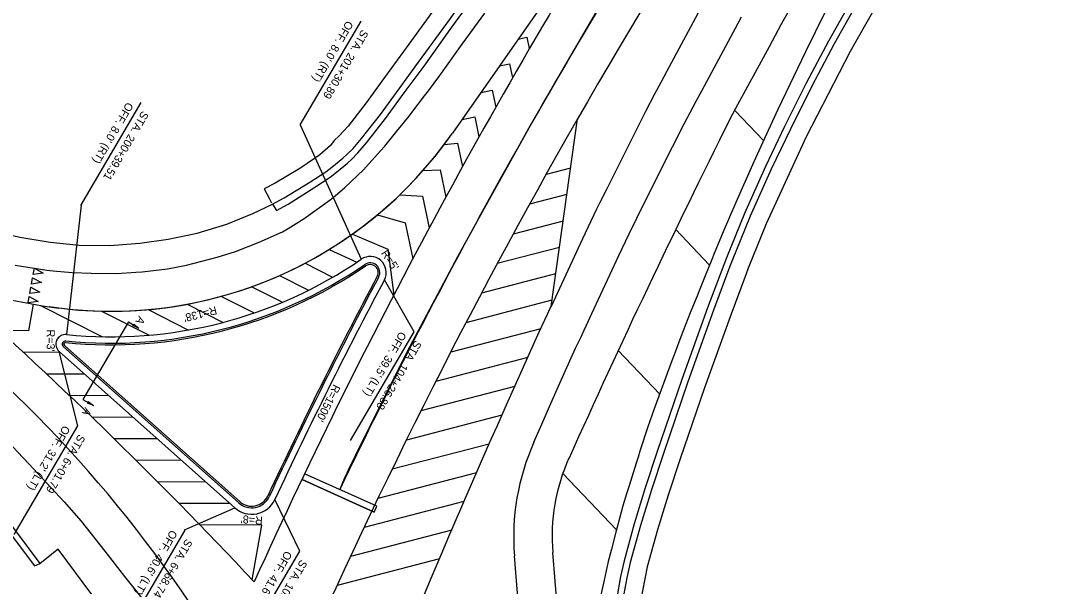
# Model space of a CAD drawing. Extents: x 1730210 to 1732101, y 650763 to 653427.
# Drawn here: x 1730371.6 to 1730692.6, y 652950.2 to 653127 of the extents above; entities that cross this region are included whole.
import ezdxf

# ---------------------------------------------------------------- set-up
doc = ezdxf.new("R2010")
doc.units = 0
for name, color, linetype in [('DESIGN - SCRATCH - User 2', 7, 'Continuous'), ('DESIGN - TRAFFIC CONTROL PERMANENT - Pavement Marking', 7, 'Continuous'), ('DESIGN - TRANSPORTATION - Curb Gutter and Sidewalk', 7, 'Continuous'), ('DESIGN - TRANSPORTATION - Edge of Traveled Way', 7, 'Continuous'), ('DESIGN - TRANSPORTATION - Text', 7, 'Continuous'), ('FUNCTIONAL - TRANSPORTATION - Pavement Marking and Traffic Control', 7, 'Continuous'), ('FUNCTIONAL - TRANSPORTATION - Preliminary Edge of Traveled Way', 7, 'Continuous'), ('SURVEY - ROADSIDE BARRIERS with Text', 7, 'Continuous'), ('SURVEY - TRANSPORTATION - Features', 7, 'Continuous')]:
    doc.layers.add(name, color=color, linetype=linetype)

msp = doc.modelspace()

# ---------------------------------------------------------------- linework, layer by layer
at = {"layer": 'DESIGN - SCRATCH - User 2'}
msp.add_lwpolyline([(1730588.17, 653054.17), (1730587.43, 653052.31), (1730585.19, 653046.75), (1730583.7, 653043.05), (1730582.96, 653041.2), (1730580.72, 653035.64), (1730579.98, 653033.79), (1730579.23, 653031.93), (1730578.49, 653030.08), (1730577.77, 653028.22), (1730575.7, 653022.59), (1730575.01, 653020.72), (1730569.51, 653005.72), (1730567.44, 653000.09), (1730565.01, 652992.48), (1730564.42, 652990.58), (1730563.82, 652988.67), (1730562.03, 652982.96), (1730561.43, 652981.05), (1730560.83, 652979.14), (1730559.66, 652975.33), (1730558.65, 652971.46), (1730557.64, 652967.6), (1730556.13, 652961.81), (1730555.12, 652957.94), (1730553.8, 652952.1), (1730552.12, 652944.29)], dxfattribs=at)
at = {"layer": 'DESIGN - TRAFFIC CONTROL PERMANENT - Pavement Marking'}
for p, q in [((1730568.54, 653180.87), (1730506.46, 653091.82)), ((1730526.94, 653121.19), (1730529.73, 653121.77)), ((1730529.73, 653121.77), (1730530.47, 653118.21)), ((1730521.11, 653112.83), (1730524.3, 653113.49)), ((1730524.3, 653113.49), (1730525.21, 653109.1)), ((1730515.28, 653104.47), (1730518.87, 653105.21)), ((1730518.87, 653105.21), (1730519.97, 653099.91)), ((1730594.64, 653098.91), (1730603.58, 653089.49)), ((1730509.45, 653096.11), (1730513.44, 653096.94)), ((1730513.44, 653096.94), (1730514.75, 653090.63)), ((1730537.24, 653037.62), (1730545.53, 653096.29)), ((1730503.86, 653088.22), (1730508.01, 653088.66)), ((1730508.01, 653088.66), (1730509.55, 653081.25)), ((1730497.32, 653080.17), (1730502.58, 653080.38)), ((1730502.58, 653080.38), (1730504.37, 653071.78)), ((1730543.35, 653080.88), (1730535.68, 653078.88)), ((1730490.01, 653072.53), (1730497.15, 653072.1)), ((1730497.15, 653072.1), (1730499.21, 653062.22)), ((1730542.19, 653072.62), (1730530.52, 653069.58)), ((1730483.01, 653066.27), (1730491.72, 653063.82)), ((1730491.72, 653063.82), (1730494.06, 653052.56)), ((1730541.02, 653064.36), (1730525.45, 653060.3)), ((1730475.21, 653060.26), (1730486.29, 653055.54)), ((1730576.18, 653061.71), (1730586.69, 653050.64)), ((1730468, 653055.48), (1730476.64, 653051.53)), ((1730486.29, 653055.54), (1730488.11, 653041.2)), ((1730539.85, 653056.1), (1730520.45, 653051.05)), ((1730460.41, 653051.15), (1730469.04, 653046.79)), ((1730452.48, 653047.31), (1730461.54, 653042.74)), ((1730538.68, 653047.84), (1730515.53, 653041.81)), ((1730443.83, 653043.84), (1730453.41, 653039)), ((1730434.29, 653040.82), (1730444.57, 653035.63)), ((1730537.52, 653039.58), (1730510.69, 653032.59)), ((1730537.52, 653039.58), (1730510.69, 653032.59)), ((1730374.16, 653030.08), (1730375.61, 653038.36)), ((1730377.79, 653038), (1730397.2, 653028.19)), ((1730396.87, 653036.2), (1730411.75, 653028.68)), ((1730411.43, 653036.69), (1730424.05, 653030.31)), ((1730423.63, 653038.37), (1730434.86, 653032.69)), ((1730374.16, 653030.08), (1730365.08, 653030.13)), ((1730534.02, 653030.71), (1730505.92, 653023.39)), ((1730383.94, 653023.33), (1730372.4, 653023.39)), ((1730558.25, 653023.94), (1730571.19, 653010.31)), ((1730529.98, 653021.7), (1730501.23, 653014.22)), ((1730391.62, 653016.5), (1730379.72, 653016.56)), ((1730525.95, 653012.7), (1730496.61, 653005.06)), ((1730399.18, 653009.76), (1730386.83, 653009.82)), ((1730406.75, 653003.02), (1730393.86, 653003.09)), ((1730521.92, 653003.69), (1730492.07, 652995.92)), ((1730414.31, 652996.28), (1730400.78, 652996.35)), ((1730517.9, 652994.69), (1730487.6, 652986.8)), ((1730421.87, 652989.54), (1730407.62, 652989.62)), ((1730513.97, 652985.71), (1730483.2, 652977.7)), ((1730540.95, 652985.52), (1730557.71, 652967.86)), ((1730429.44, 652982.8), (1730414.36, 652982.88)), ((1730482.06, 652973.4), (1730459.48, 652983.59)), ((1730437, 652976.06), (1730421.02, 652976.15)), ((1730510.05, 652976.73), (1730478.86, 652968.61)), ((1730446.88, 652969.31), (1730427.59, 652969.41)), ((1730443.91, 652952.29), (1730446.88, 652969.31)), ((1730506.22, 652967.77), (1730474.6, 652959.54)), ((1730534.26, 652857.53), (1730525.83, 652959.78)), ((1730546.22, 652858.52), (1730537.78, 652960.76)), ((1730502.38, 652958.82), (1730470.41, 652950.5))]:
    msp.add_line(p, q, dxfattribs=at)
for points in [[(1730593.11, 653096.12), (1730595.01, 653099.58), (1730605.44, 653118.92), (1730606.39, 653120.68), (1730607.32, 653122.42), (1730609.17, 653125.81), (1730610.1, 653127.46), (1730620.96, 653146.57), (1730627.78, 653158.58), (1730630.78, 653163.54), (1730640.18, 653178.84), (1730649.49, 653194.01), (1730672.51, 653228.86), (1730678.04, 653237.13), (1730683.11, 653244.69)], [(1730594.14, 653148.92), (1730588.79, 653139.5), (1730587.75, 653137.67), (1730585.78, 653134.04), (1730584.82, 653132.27), (1730583.87, 653130.51), (1730573.44, 653111.17), (1730571.55, 653107.65), (1730569.6, 653104.04), (1730566.77, 653098.56), (1730554.35, 653073.78)], [(1730369.89, 653050.6), (1730375.78, 653049.62), (1730379.73, 653049.04), (1730381.71, 653048.83), (1730387.67, 653048.28), (1730393.64, 653048.02), (1730401.62, 653047.99), (1730407.59, 653048.35), (1730409.58, 653048.47), (1730417.49, 653049.46), (1730423.37, 653050.53), (1730433, 653053.08), (1730438.71, 653054.8), (1730446.12, 653057.73), (1730453.4, 653060.99), (1730455.1, 653062.03), (1730460.19, 653065.18), (1730463.45, 653067.5), (1730468.3, 653071), (1730469.84, 653072.28), (1730472.9, 653074.84), (1730478.67, 653080.37), (1730484.04, 653086.28), (1730485.38, 653087.77), (1730489.14, 653092.44), (1730492.9, 653097.1), (1730494.12, 653098.67), (1730497.78, 653103.42), (1730499, 653105), (1730502.51, 653109.86), (1730509.49, 653119.6), (1730516.54, 653129.3)], [(1730471.25, 652980.39), (1730472.79, 652983.87), (1730473.6, 652985.7), (1730474.44, 652987.51), (1730476.13, 652991.13), (1730481.48, 653001.85), (1730492.24, 653023.27), (1730494.09, 653026.81), (1730508.17, 653053.26), (1730514.89, 653065.53), (1730530.41, 653093.47), (1730534.41, 653100.39), (1730542.44, 653114.2), (1730551.48, 653129.75)], [(1730531.92, 652995.23), (1730534.34, 653000.89), (1730536.79, 653006.36), (1730540.05, 653013.65), (1730544.94, 653024.59), (1730546.63, 653028.21), (1730547.47, 653030.02), (1730548.32, 653031.83), (1730550, 653035.45), (1730558.43, 653053.55), (1730562.7, 653062.58), (1730563.59, 653064.36), (1730564.49, 653066.15), (1730575.23, 653087.57), (1730577.02, 653091.14), (1730577.91, 653092.92), (1730580.66, 653098.25), (1730581.6, 653100.01), (1730582.55, 653101.76), (1730584.45, 653105.28), (1730594.88, 653124.62), (1730595.82, 653126.38), (1730596.77, 653128.13)], [(1730554.35, 653073.78), (1730552.42, 653069.94), (1730551.46, 653068.02), (1730547.12, 653058.84), (1730537.24, 653037.62)], [(1730279.88, 653060.81), (1730281.86, 653059.79), (1730290.11, 653055.41), (1730298.77, 653050.43), (1730306.79, 653045.43), (1730315.16, 653039.98), (1730322.67, 653034.75), (1730331.63, 653027.94), (1730338.9, 653022.07), (1730346.44, 653015.53), (1730353.22, 653009.5), (1730360.49, 653002.64), (1730367.3, 652995.75), (1730374.2, 652988.52), (1730385.19, 652976.62)], [(1730518.03, 652994.99), (1730518.04, 652995.02), (1730519.68, 652998.69), (1730520.5, 653000.51), (1730522.95, 653005.98), (1730533.58, 653029.76), (1730535.31, 653033.47), (1730536.15, 653035.28), (1730536.99, 653037.09), (1730537.24, 653037.62)], [(1730459.75, 652854.49), (1730462.34, 652861.01), (1730463.81, 652864.72), (1730464.55, 652866.58), (1730467.49, 652874.01), (1730478.69, 652901.8), (1730487.06, 652922.11), (1730491.64, 652933.19), (1730494.71, 652940.56), (1730500.09, 652953.46), (1730503.24, 652960.81), (1730505.59, 652966.32), (1730506.38, 652968.16), (1730507.95, 652971.83), (1730508.73, 652973.66), (1730510.3, 652977.33), (1730518.04, 652995.02)], [(1730385.19, 652976.62), (1730390.46, 652970.6), (1730397.86, 652961.16), (1730404.04, 652953.3), (1730407.74, 652948.58), (1730408.98, 652947.01), (1730410.08, 652945.35), (1730414.32, 652938.57), (1730416.33, 652935.1), (1730417.24, 652933.33), (1730418.1, 652931.52), (1730418.91, 652929.69), (1730420.24, 652925.92), (1730421.36, 652922.08), (1730421.91, 652920.16), (1730422.75, 652916.25), (1730423.43, 652910.3), (1730423.58, 652908.3), (1730423.67, 652903.38)]]:
    msp.add_lwpolyline(points, dxfattribs=at)
for points in [[(1730375.53, 653047.62), (1730375.89, 653049.59), (1730378.67, 653048.06)], [(1730374.99, 653044.67), (1730375.35, 653046.63), (1730378.13, 653045.11)], [(1730374.45, 653041.72), (1730374.81, 653043.68), (1730377.59, 653042.16)], [(1730373.91, 653038.76), (1730374.27, 653040.73), (1730377.05, 653039.21)], [(1730482.06, 652973.4), (1730482.88, 652975.22), (1730460.3, 652985.41), (1730459.48, 652983.59)]]:
    msp.add_lwpolyline(points, close=True, dxfattribs=at)
for centre, radius, start, end in [((1732146.89, 652178.93), 1845.51, 143.31109, 155.90666), ((1732146.89, 652178.93), 1869.51, 147.59272, 155.58683), ((1733115.88, 651833.24), 2821.21, 153.40774, 155.78687), ((1730399.81, 653166.17), 130.01, 261.4471, 325.1194), ((1730399.81, 653166.17), 130, 262.7955, 325.1194), ((1730406.08, 653215.77), 180.01, 251.24, 262.7955), ((1729392.41, 651966.14), 1441.58, 43.127, 48.47054), ((1730082.94, 652714.55), 412, 31.4096, 52.3723), ((1730597.58, 652965.7), 72, 155.7869, 184.7177), ((1730597.58, 652965.7), 60, 155.7869, 184.7177)]:
    msp.add_arc(centre, radius, start, end, dxfattribs=at)
at = {"layer": 'DESIGN - TRANSPORTATION - Curb Gutter and Sidewalk'}
for p, q in [((1730383.59, 653023.64), (1730438.45, 652974.77)), ((1730384.92, 653025.14), (1730439.78, 652976.27)), ((1730385.25, 653025.51), (1730440.11, 652976.64))]:
    msp.add_line(p, q, dxfattribs=at)
for centre, radius, start, end in [((1730399.81, 653166.17), 138, 264.2103, 304.4848), ((1730480.77, 653048.29), 5, 332.0531, 124.4848), ((1730399.81, 653166.17), 140.5, 264.2103, 304.472), ((1730399.81, 653166.17), 140, 264.2103, 304.472), ((1730480.77, 653048.29), 3, 332.0531, 124.4848), ((1730480.77, 653048.29), 2.5, 332.0531, 124.4848), ((1731810.26, 652342.97), 1502.5, 152.05305, 154.98031), ((1731810.26, 652342.97), 1502, 152.05305, 154.98031), ((1731810.26, 652342.97), 1500, 152.05305, 154.98031), ((1730385.59, 653025.88), 3, 84.2103, 228.3045), ((1730385.59, 653025.88), 1, 84.2103, 228.3045), ((1730385.59, 653025.88), 0.5, 84.2103, 228.3045), ((1730443.77, 652980.75), 5.5, 228.3045, 334.9803), ((1730443.77, 652980.75), 8, 228.3045, 334.9803), ((1730443.77, 652980.75), 6, 228.3045, 334.9803)]:
    msp.add_arc(centre, radius, start, end, dxfattribs=at)
at = {"layer": 'DESIGN - TRANSPORTATION - Edge of Traveled Way'}
for points in [[(1730685.53, 653248.11), (1730680.77, 653239.34), (1730670.06, 653220.12), (1730660.59, 653202.51), (1730654.94, 653191.92), (1730650.25, 653183.09), (1730645.61, 653174.24), (1730639.17, 653161.81), (1730632.82, 653149.35), (1730631.91, 653147.57), (1730628.28, 653140.45), (1730624.67, 653133.32), (1730623.78, 653131.53), (1730622.89, 653129.74), (1730616.69, 653117.22), (1730608.05, 653099.23), (1730603.89, 653090.16), (1730600.58, 653082.9), (1730594.95, 653070.11), (1730591.02, 653060.94), (1730588.7, 653055.42), (1730588.17, 653054.17)], [(1730588.17, 653054.17), (1730587.43, 653052.31), (1730585.19, 653046.75), (1730583.7, 653043.05), (1730582.96, 653041.2), (1730580.72, 653035.64), (1730579.98, 653033.79), (1730579.23, 653031.93), (1730578.49, 653030.08), (1730577.77, 653028.22), (1730575.7, 653022.59), (1730575.01, 653020.72), (1730569.51, 653005.72), (1730567.44, 653000.09), (1730565.01, 652992.48), (1730564.42, 652990.58), (1730563.82, 652988.67), (1730562.03, 652982.96), (1730561.43, 652981.05), (1730560.83, 652979.14), (1730559.66, 652975.33), (1730558.65, 652971.46), (1730557.64, 652967.6), (1730556.13, 652961.81), (1730555.12, 652957.94), (1730553.8, 652952.1), (1730552.12, 652944.29)]]:
    msp.add_lwpolyline(points, dxfattribs=at)
at = {"layer": 'DESIGN - TRANSPORTATION - Text'}
for p, q in [((1730458.91, 653094.42), (1730477.93, 653126.84)), ((1730390.36, 653069.16), (1730409.27, 653101.39)), ((1730405.26, 653032.85), (1730391.04, 653008.62)), ((1730405.26, 653032.85), (1730408.53, 653030.93)), ((1730474.58, 652995.74), (1730494.53, 653029.74)), ((1730391.04, 653008.62), (1730394.3, 653006.7)), ((1730369.55, 652966.4), (1730389.5, 653000.4)), ((1730403.05, 652933.75), (1730423, 652967.74)), ((1730438.87, 652927.22), (1730458.82, 652961.22))]:
    msp.add_line(p, q, dxfattribs=at)
for points in [[(1730458.91, 653094.42), (1730477.94, 653052.42)], [(1730390.47, 653069.35), (1730385.89, 653028.87)], [(1730494.53, 653029.74), (1730485.19, 653045.95)], [(1730408.53, 653030.93), (1730406.67, 653031.74), (1730407.02, 653031.82), (1730406.92, 653032.18), (1730408.53, 653030.93)], [(1730389.5, 653000.4), (1730383.59, 653023.64)], [(1730394.3, 653006.7), (1730392.44, 653007.5), (1730392.8, 653007.59), (1730392.7, 653007.94), (1730394.3, 653006.7)], [(1730458.82, 652961.22), (1730451.02, 652977.36)], [(1730422.81, 652967.85), (1730438.45, 652974.77)]]:
    msp.add_lwpolyline(points, dxfattribs=at)
for points in [[(1730408.53, 653030.93), (1730406.67, 653031.74), (1730407.02, 653031.82), (1730406.92, 653032.18)], [(1730394.3, 653006.7), (1730392.44, 653007.5), (1730392.8, 653007.59), (1730392.7, 653007.94)]]:
    msp.add_lwpolyline(points, close=True, dxfattribs=at)
at = {"layer": 'FUNCTIONAL - TRANSPORTATION - Pavement Marking and Traffic Control'}
for centre, radius, start, end in [((1732146.89, 652178.93), 1869.51, 147.59272, 155.58683), ((1732134.98, 652182.29), 1845.28, 147.53511, 154.37062), ((1730399.81, 653166.17), 130.01, 261.4471, 325.1194), ((1729392.41, 651966.14), 1441.58, 43.127, 48.47054)]:
    msp.add_arc(centre, radius, start, end, dxfattribs=at)
at = {"layer": 'FUNCTIONAL - TRANSPORTATION - Preliminary Edge of Traveled Way'}
for p, q in [((1730383.59, 653023.64), (1730438.45, 652974.77)), ((1730384.92, 653025.14), (1730439.78, 652976.27)), ((1730385.25, 653025.51), (1730440.11, 652976.64))]:
    msp.add_line(p, q, dxfattribs=at)
for centre, radius, start, end in [((1730399.81, 653166.17), 138, 264.2103, 304.4848), ((1730480.77, 653048.29), 5, 332.0531, 124.4848), ((1730399.81, 653166.17), 140.5, 264.2103, 304.472), ((1730399.81, 653166.17), 140, 264.2103, 304.472), ((1730480.77, 653048.29), 3, 332.0531, 124.4848), ((1730480.77, 653048.29), 2.5, 332.0531, 124.4848), ((1731810.26, 652342.97), 1502.5, 152.05305, 154.98031), ((1731810.26, 652342.97), 1502, 152.05305, 154.98031), ((1731810.26, 652342.97), 1500, 152.05305, 154.98031), ((1730385.59, 653025.88), 3, 84.2103, 228.3045), ((1730385.59, 653025.88), 1, 84.2103, 228.3045), ((1730385.59, 653025.88), 0.5, 84.2103, 228.3045), ((1730443.77, 652980.75), 5.5, 228.3045, 334.9803), ((1730443.77, 652980.75), 8, 228.3045, 334.9803), ((1730443.77, 652980.75), 6, 228.3045, 334.9803)]:
    msp.add_arc(centre, radius, start, end, dxfattribs=at)
at = {"layer": 'SURVEY - ROADSIDE BARRIERS with Text'}
for points in [[(1730244.35, 653065.91), (1730258.67, 653059.93), (1730272.72, 653053.24), (1730286.26, 653046.01), (1730299.37, 653037.63), (1730311.67, 653028.09), (1730323.76, 653017.4), (1730335.29, 653006.23), (1730342, 652999.15), (1730347.05, 652993.36), (1730353.48, 652985.73), (1730363.57, 652972.96), (1730368.32, 652966.74), (1730375.88, 652956.6), (1730377.65, 652957.37)], [(1730377.65, 652957.37), (1730370.05, 652967.58), (1730365.29, 652973.88), (1730355.2, 652986.83), (1730348.75, 652994.6), (1730343.7, 653000.38), (1730336.88, 653007.54), (1730325.24, 653018.88), (1730312.96, 653029.7), (1730300.57, 653039.33), (1730287.37, 653047.78), (1730273.76, 653055.04), (1730259.59, 653061.77), (1730245.17, 653067.81)]]:
    msp.add_lwpolyline(points, dxfattribs=at)
at = {"layer": 'SURVEY - TRANSPORTATION - Features'}
for points in [[(1730609.43, 653269.39), (1730601.62, 653259.61), (1730582.78, 653236.22), (1730563.72, 653213.03), (1730544.77, 653189.68), (1730535.59, 653177.78), (1730526.59, 653165.78), (1730517.68, 653153.72), (1730508.84, 653141.61), (1730500.05, 653129.49), (1730491.2, 653117.35), (1730485.19, 653109.17), (1730479.55, 653101.28), (1730473.84, 653094.03), (1730471.07, 653090.99), (1730469.52, 653089.49), (1730468.39, 653087.93), (1730465.09, 653085.08), (1730463.42, 653083.93), (1730458.79, 653080.79), (1730451.04, 653076.23), (1730447.64, 653074.44), (1730449.28, 653071.25), (1730449.99, 653070.09)], [(1730450.28, 653069.61), (1730451.48, 653067.67), (1730455.12, 653069.61), (1730463.19, 653074.69), (1730468.27, 653078.11), (1730470.28, 653079.67), (1730473.67, 653082.43), (1730475.07, 653083.7), (1730476.9, 653085.7), (1730479.63, 653088.77), (1730485.55, 653096.44), (1730491.43, 653104.37), (1730497.58, 653112.74), (1730506.29, 653124.96), (1730515.08, 653137.08), (1730523.91, 653149.2), (1730532.8, 653161.27), (1730541.82, 653173.25), (1730550.93, 653185.18), (1730569.79, 653208.56), (1730589, 653231.66), (1730607.41, 653253.55)], [(1730692.6, 653239.86), (1730691.68, 653238.27), (1730684.07, 653225.34), (1730672.24, 653204.84), (1730657.33, 653178.8), (1730642.49, 653153.3), (1730635.02, 653140.26), (1730633.02, 653136.9), (1730623.9, 653120.58), (1730616.91, 653107.48), (1730610.21, 653093.94), (1730604.2, 653081.41), (1730597.65, 653066.76), (1730592.04, 653052.85)], [(1730450.28, 653069.61), (1730453.92, 653071.56), (1730461.92, 653076.45), (1730466.92, 653079.74), (1730468.8, 653081.21), (1730472.19, 653083.96), (1730473.59, 653085.25), (1730475.4, 653087.06), (1730478.09, 653090.16), (1730484.04, 653097.66), (1730489.82, 653105.61), (1730495.87, 653113.98), (1730504.68, 653126.12), (1730513.47, 653138.25)], [(1730634.86, 653136.02), (1730625.71, 653119.71), (1730618.7, 653106.52), (1730611.99, 653093.08), (1730605.99, 653080.51), (1730599.46, 653065.89), (1730593.81, 653052)], [(1730639.85, 653133.62), (1730630.65, 653117.34), (1730616.96, 653090.7), (1730604.4, 653063.52), (1730598.78, 653049.61)], [(1730253.82, 653114.13), (1730267.75, 653108.61), (1730281.81, 653102.2), (1730295.59, 653095.65), (1730308.55, 653088.68), (1730321.61, 653081.2), (1730334.49, 653074.04), (1730347.31, 653067.34), (1730353.58, 653064.62), (1730362.5, 653061.44), (1730371.34, 653059.29), (1730380.86, 653057.75), (1730389.87, 653056.86), (1730399.5, 653056.72), (1730408.84, 653057.42), (1730417.67, 653058.69), (1730426.73, 653060.57), (1730435.96, 653063.41), (1730444.1, 653066.73), (1730450.28, 653069.61)], [(1730592.04, 653052.85), (1730591.18, 653050.64), (1730586.09, 653037.26), (1730578.08, 653014.81), (1730570.43, 652992.33), (1730566.69, 652980.98), (1730563.23, 652969.76), (1730560.07, 652958.21), (1730558.94, 652953.33), (1730557.81, 652946.66), (1730556.25, 652934.99), (1730555.09, 652923.03), (1730554.38, 652914.72)], [(1730593.81, 653052), (1730593.01, 653049.91), (1730587.95, 653036.51), (1730579.97, 653014.12), (1730572.35, 652991.72), (1730568.61, 652980.38), (1730565.18, 652969.25), (1730561.99, 652957.71), (1730560.9, 652952.93), (1730559.72, 652946.25), (1730558.22, 652934.65), (1730557.04, 652922.7), (1730556.4, 652914.49)], [(1730598.78, 653049.61), (1730598.21, 653047.82), (1730593.16, 653034.42), (1730585.23, 653012.19), (1730577.61, 652990.04), (1730573.85, 652978.74), (1730570.46, 652967.88), (1730567.29, 652956.32), (1730565.12, 652945.09), (1730563.69, 652933.72), (1730562.37, 652921.79), (1730561.79, 652913.85)], [(1730395.47, 652945.52), (1730393.84, 652947.63), (1730383.29, 652961.88), (1730377.65, 652957.37)]]:
    msp.add_lwpolyline(points, dxfattribs=at)

# ---------------------------------------------------------------- texts
at = {"layer": 'DESIGN - TRANSPORTATION - Text'}
for s, rotation, p in [("OFF. 8.0' (RT)", 239.5926, (1730473.47, 653127.14)), ('STA. 201+30.89', 239.5926, (1730478.21, 653124.35)), ("OFF. 8.0' (RT)", 239.5926, (1730404.81, 653101.69)), ('STA. 200+39.51', 239.5926, (1730409.55, 653098.91)), ("R=5'", 303.3838, (1730484.05, 653054.31)), ("R=138'", 194.2868, (1730432.51, 653037.76)), ('A', 239.5926, (1730408.52, 653034.88)), ("R=3'", 270.0424, (1730379.76, 653030.44)), ("OFF. 39.5' (LT)", 239.5926, (1730490.07, 653030.04)), ('STA. 104+26.88', 239.5926, (1730494.81, 653027.25)), ("R=1500'", 243.4147, (1730469.35, 653013.55)), ('A', 239.5926, (1730391.75, 653006.3)), ("OFF. 31.2' (LT)", 239.5926, (1730385.04, 653000.7)), ('STA. 6+01.79', 239.5926, (1730389.78, 652997.92)), ("R=8'", 175.8118, (1730447.29, 652971.97)), ("OFF. 40.6' (LT)", 239.5926, (1730418.54, 652968.04)), ('STA. 6+68.74', 239.5926, (1730423.28, 652965.26)), ("OFF. 41.6' (LT)", 239.5926, (1730454.36, 652961.52)), ('STA. 103+52.17', 239.5926, (1730459.1, 652958.73))]:
    msp.add_text(s, height=2.5, rotation=rotation, dxfattribs=at).set_placement(p)

doc.saveas('drawing.dxf')
